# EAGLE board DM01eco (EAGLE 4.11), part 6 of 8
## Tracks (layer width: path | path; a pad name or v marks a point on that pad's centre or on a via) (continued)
DB11-0  (via drill 0.61) (continued)
  Route2 0.152: v163.19,13.97 168.28,13.97 175.26,20.95 181.61,20.95 187.96,27.3 189.87,27.3 192.41,24.77 194.31,26.67 200.03,26.67 200.66,27.3 209.55,27.3 211.46,25.4 255.27,69.22 v255.27,69.85
  Route15 0.152: v67.31,99.06 67.94,99.06 74.3,92.71 74.93,92.71 76.2,91.44 76.2,89.54 89.53,76.2 89.53,75.57 92.08,73.03 93.34,73.03 98.42,67.95 99.69,67.95 v101.6,66.04 | v125.09,42.55 130.18,42.55 147.96,24.77 148.59,24.77 159.38,13.97 v163.19,13.97
  Bottom 0.152: v67.31,99.06 45.72,120.65 48.26,123.19 52.07,123.19 C28.F2 | v101.6,66.04 101.6,65.41 124.46,42.55 v125.09,42.55 | v255.27,69.85 258.44,73.03 269.88,61.59 269.88,59.69 267.97,57.78 269.88,55.88 269.88,55.24 278.13,46.99 v278.13,46.35
DB11-1  (via drill 0.61)
  Top 0.152: v48.26,85.09 58.42,95.25 53.98,99.7 50.8,99.7 46.35,95.25 41.27,100.33 41.27,102.87 52.7,114.3 52.7,116.84 C28.J2 | v165.74,1.91 166.37,1.91 167.64,3.18 169.54,3.18 191.77,25.4 192.41,25.4 203.2,36.2 208.91,36.2 219.07,46.35 219.07,48.89 220.34,50.16 D15.H2
  Route15 0.152: v116.2,24.13 123.19,24.13 130.18,17.14 130.18,15.88 131.44,14.61 133.35,14.61 133.99,13.97 153.67,13.97 v155.57,12.07
  Bottom 0.152: v48.26,85.09 48.26,81.28 59.05,70.48 62.23,73.66 69.85,66.04 69.85,65.41 88.9,46.35 94.61,46.35 116.2,24.77 v116.2,24.13 | v165.74,1.91 v155.57,12.07
DB11-2  (via drill 0.61)
  Top 0.152: v127,34.92 127,35.56 127.64,36.2 132.72,36.2 145.41,48.89 145.41,49.53 146.69,50.8 147.32,50.8 151.13,46.99 153.03,48.89 155.57,48.89 156.84,50.16 D20.H2
  Route15 0.152: v120.02,40.64 124.46,36.2 125.73,36.2 v127,34.92
  Bottom 0.152: v120.02,40.64 117.47,43.18 117.47,48.89 104.78,61.59 98.42,61.59 52.7,107.32 52.7,110.49 C28.L2
DB11-3
  Bottom 0.152: D25.H2 93.34,51.43 93.34,53.98 57.15,90.17 57.15,91.44 56.52,92.08 56.52,93.98 58.42,95.89 53.98,100.33 53.98,102.87 52.7,104.14 C28.N2
DB11-4  (via drill 0.61)
  Top 0.152: v28.57,66.67 28.57,71.75 51.44,94.62 51.44,97.16 52.07,97.79 C28.R2
  Bottom 0.152: v28.57,66.67 28.57,56.52 29.84,55.24 29.84,51.43 D30.H2
DB11-5  (via drill 0.61)
  Top 0.152: v14.61,142.88 14.61,149.22 11.43,152.4 v43.81,184.78 | v53.98,222.25 55.24,222.25 66.67,233.68 66.67,240.03 79.38,252.73 79.38,255.27 80.64,256.54 A26.H2
  Route2 0.152: v53.98,95.89 52.7,94.62 52.7,92.71 C28.T2 | v43.81,184.78 50.8,191.77 50.8,193.04 53.98,196.22 v53.98,222.25
  Bottom 0.152: v53.98,95.89 55.88,97.79 44.45,109.22 38.73,109.22 15.88,132.08 15.88,141.61 v14.61,142.88
DB11-6  (via drill 0.61)
  Top 0.152: v55.24,87 53.34,87 52.7,86.36 C28.V2
  Route2 0.152: v27.3,182.25 27.3,180.97 15.88,169.55 15.88,156.21 v7.62,147.96
  Route15 0.152: v27.3,182.25 28.57,183.52 28.57,204.47 3.17,229.87 3.17,241.94 1.27,243.84 13.97,256.54 17.14,256.54 A31.H2
  Bottom 0.152: v7.62,147.96 7.62,139.7 53.98,93.34 53.98,88.27 v55.24,87
DB_SEL_DEV0  (via drill 0.61)
  Top 0.152: C17.E2 194.94,126.37 193.68,125.09 191.13,125.09 189.23,123.19 186.06,126.37 182.88,126.37 C18.E2 182.25,126.37 179.71,126.37 176.53,123.19 179.71,120.02 v177.8,118.11 | 69.85,126.37 71.75,126.37 74.93,123.19 76.83,125.09 79.38,125.09 80.64,126.37 C26.E2 | 69.85,126.37 68.58,126.37 C27.E2 | C19.E2 169.54,127.64 168.28,128.91 162.56,128.91 161.29,127.64 157.48,127.64 C20.E2 156.84,126.37 153.67,126.37 148.59,121.29 v148.59,120.65 | C25.E2 93.98,127.64 97.79,127.64 99.06,128.91 104.78,128.91 106.05,127.64 C24.E2 106.68,127 109.86,127 111.76,128.91 118.11,128.91 119.38,127.64 C23.E2 | v137.79,122.56 142.88,127.64 144.15,127.64 C21.E2 | 69.85,126.37 v65.41,121.92 | v268.61,275.59 267.33,275.59 262.89,271.14 262.25,271.14 259.71,268.6 257.18,268.6 255.91,267.33 A12.D2
  Route2 0.152: C28.E2 55.24,127.64 51.44,127.64 48.9,130.18 46.99,128.27 43.81,128.27 43.18,127.64 C29.E2 | v296.55,241.94 296.55,241.3 271.14,215.9 271.14,208.91 247.65,185.42 247.65,184.78 244.47,181.61 244.47,177.16 243.84,176.53 238.12,176.53 216.53,154.94 216.53,153.67 208.91,146.05 208.91,144.15 199.39,134.62 198.75,134.62 194.94,130.81 194.94,127.64 C17.E2
  Route15 0.152: v350.52,200.66 353.69,197.49 356.87,197.49 B04.D2
  Bottom 0.152: C30.E2 30.48,126.37 34.29,126.37 35.56,125.09 41.27,125.09 42.55,126.37 C29.E2 | 130.18,125.09 124.46,125.09 123.19,126.37 119.38,126.37 C23.E2 | 130.18,125.09 131.44,126.37 C22.E2 | v137.79,122.56 136.53,122.56 134.62,120.65 130.18,125.09 | v148.59,120.65 147.96,120.65 145.41,123.19 145.41,125.73 144.78,126.37 C21.E2 | C26.E2 81.28,126.37 85.09,126.37 86.36,125.09 92.08,125.09 93.34,126.37 C25.E2 | v177.8,118.11 179.71,120.02 173.99,125.73 170.81,125.73 170.18,126.37 C19.E2 | v65.41,121.92 64.77,122.56 63.5,122.56 59.69,126.37 55.88,126.37 C28.E2 | v350.52,200.66 349.25,200.66 345.44,204.47 340.36,204.47 299.72,245.11 | 299.72,245.11 287.02,257.81 286.38,257.81 v268.61,275.59 | 299.72,245.11 v296.55,241.94
DB_SEL_DEV1  (via drill 0.61)
  Top 0.152: C20.H2 157.48,121.29 161.29,121.29 162.56,122.56 168.28,122.56 169.54,121.29 C19.H2 | C29.H2 43.18,121.29 43.81,121.92 46.99,121.92 48.9,123.83 51.44,121.29 55.24,121.29 C28.H2 55.88,120.02 59.05,120.02 62.23,116.84 64.14,118.75 65.41,118.75 67.94,121.29 C27.H2 | C23.H2 119.38,121.29 123.19,121.29 124.46,122.56 130.18,122.56 131.44,121.29 C22.H2 | 91.44,121.29 89.53,121.29 87,123.83 85.09,121.92 81.92,121.92 81.28,121.29 C26.H2 | 91.44,121.29 93.34,121.29 C25.H2 | 91.44,121.29 97.16,127 102.87,121.29 106.05,121.29 C24.H2 | v148.59,127.64 145.41,124.46 145.41,121.92 144.78,121.29 C21.H2 | v348.62,203.84 348.62,202.56 347.98,201.93 349.88,200.03 347.98,198.12 v347.35,198.12 | v355.6,188.59 356.87,189.87 B04.F2 | v194.94,202.56 194.94,203.84 196.85,205.74 196.85,209.55 v206.38,219.08
  Route2 0.152: C17.H2 194.94,121.29 191.13,121.29 188.59,123.83 184.78,120.02 182.88,120.02 C18.H2 | C21.H2 144.15,120.02 140.34,120.02 139.06,118.75 137.16,118.75 133.35,122.56 132.08,121.29 C22.H2 | 257.18,267.97 257.18,271.14 264.16,278.13 276.86,278.13 v278.13,279.4 | 257.18,267.97 257.18,264.8 255.91,263.52 255.91,260.99 A12.F2 | v165.1,147.32 166.37,148.59 166.37,149.86 171.45,154.94 171.45,158.12 170.18,159.39 175.26,164.47 175.26,166.37 173.35,168.28 175.9,170.81 176.53,170.81 177.8,172.09 177.8,173.99 180.97,177.16 180.97,182.88 193.68,195.58 193.68,201.3 v194.94,202.56 | v206.38,219.08 206.38,221.62 211.46,226.69 212.72,226.69 254,267.97 257.18,267.97
  Bottom 0.152: 173.99,132.08 182.25,123.83 182.25,121.29 C18.H2 | 173.99,132.08 172.09,132.08 166.37,126.37 168.28,124.46 168.28,122.56 169.54,121.29 C19.H2 | C30.H2 30.48,120.02 34.29,120.02 35.56,118.75 41.91,118.75 43.18,120.02 C29.H2 | C27.H2 68.58,120.02 72.39,120.02 73.66,118.75 80.01,118.75 81.28,120.02 C26.H2 | C23.H2 118.75,121.29 114.94,121.29 113.67,122.56 111.12,122.56 107.95,119.38 106.68,120.65 C24.H2 | v148.59,127.64 148.59,126.37 149.86,125.09 150.5,125.09 154.31,121.29 156.84,121.29 C20.H2 | v278.13,279.4 330.2,227.33 330.2,226.06 333.38,222.89 333.38,217.81 346.07,205.11 347.35,205.11 v348.62,203.84 | v347.35,198.12 347.35,196.85 v355.6,188.59 | 173.99,132.08 173.99,134.62 175.9,136.53 v165.1,147.32
DB_SEL_DEV2  (via drill 0.61)
  Top 0.152: C18.K2 182.25,114.94 180.97,116.21 175.26,116.21 173.99,114.94 170.18,114.94 C19.K2 169.54,113.67 167,113.67 v163.83,110.49 | 119.38,117.48 119.38,114.94 C23.K2 | 119.38,117.48 121.28,119.38 123.83,119.38 130.18,113.03 131.44,114.3 C22.K2 | 92.08,116.21 92.71,116.21 93.98,114.94 C25.K2 | 92.08,116.21 86.36,116.21 85.09,114.94 81.28,114.94 C26.K2 80.64,113.67 76.83,113.67 75.56,112.4 73.03,112.4 69.85,115.57 68.58,114.3 C27.K2 67.94,113.67 66.67,112.4 64.14,112.4 62.23,110.49 59.05,113.67 55.88,113.67 C28.K2 | 92.08,116.21 96.52,120.65 102.23,114.94 106.05,114.94 C24.K2 | 119.38,117.48 116.2,120.65 109.22,113.67 v109.22,113.03 | 259.71,261.62 276.86,278.76 276.86,279.4 278.13,280.67 v285.75,280.67 | 259.71,261.62 255.91,257.81 255.91,254.64 A12.J2 | v373.38,196.22 368.94,191.77 367.67,191.77 361.95,186.06 358.77,186.06 357.5,184.78 B04.J2 | v165.1,148.59 165.74,148.59 168.28,151.13 169.54,149.86 169.54,149.22 165.74,145.41 165.74,139.06 144.78,118.11 144.78,114.94 C21.K2 | v219.07,256.54 219.07,258.44 231.14,270.51 v231.78,270.51 | v249.56,255.91 249.56,257.18 251.46,259.08 252.09,259.08 254.63,261.62 259.71,261.62
  Route2 0.152: C17.K2 194.94,114.94 191.13,114.94 188.59,117.48 186.69,115.57 183.51,115.57 182.88,114.94 C18.K2 | C30.K2 30.48,114.94 34.29,114.94 35.56,116.21 41.91,116.21 43.18,114.94 C29.K2 | v165.1,148.59 165.1,154.94 165.74,155.58 165.74,156.21 153.67,168.28 155.57,170.18 155.57,183.52 160.66,188.59 161.29,188.59 193.68,220.98 193.68,227.33 219.07,252.73 v219.07,256.54
  Route15 0.152: C29.K2 43.18,113.67 46.99,113.67 48.26,112.4 54.61,112.4 55.88,113.67 C28.K2
  Bottom 0.152: C22.K2 132.08,114.94 133.99,113.03 137.16,116.21 139.06,116.21 140.34,114.94 144.15,114.94 C21.K2 144.78,114.94 146.69,113.03 149.86,116.21 151.76,116.21 153.03,114.94 156.84,114.94 C20.K2 157.48,113.67 158.12,113.03 161.29,113.03 v163.83,110.49 | v109.22,113.03 107.31,113.03 106.68,113.67 C24.K2 | v285.75,280.67 289.56,280.67 332.74,237.49 332.74,236.86 v373.38,196.22 | v231.78,270.51 232.41,271.14 234.95,271.14 247.01,259.08 247.01,258.44 v249.56,255.91
DB_SEL_DEV3  (via drill 0.61)
  Top 0.152: v46.35,102.87 47.62,102.87 50.8,106.05 53.98,106.05 55.24,107.32 C28.M2 | C26.M2 80.64,108.59 76.83,108.59 74.3,111.12 72.39,109.22 69.22,109.22 68.58,108.59 C27.M2 | 183.51,109.22 180.34,112.4 178.44,112.4 176.53,110.49 175.9,110.49 173.99,108.59 170.18,108.59 C19.M2 169.54,107.32 165.74,107.32 v162.56,104.14 | 183.51,109.22 182.88,108.59 C18.M2 | v189.87,104.78 192.41,107.32 194.94,107.32 C17.M2 | 183.51,109.22 v184.15,109.86 | C24.M2 106.68,107.32 109.86,107.32 113.03,104.14 114.94,106.05 117.47,106.05 118.75,107.32 C23.M2 | v125.73,104.14 128.91,107.32 131.44,107.32 C22.M2 | v138.43,98.43 144.15,104.14 144.15,107.32 C21.M2 144.78,107.32 147.96,107.32 150.5,104.78 151.76,106.05 155.57,106.05 156.84,107.32 C20.M2 157.48,108.59 157.48,111.12 v164.47,118.11 | v109.22,115.57 109.22,114.94 104.14,109.86 99.06,109.86 97.79,108.59 93.98,108.59 C25.M2 | v344.81,162.56 356.87,174.62 356.87,177.16 B04.L2 | v156.84,142.88 156.84,145.41 175.9,164.47 175.9,165.1 v178.44,167.64
  Route2 0.152: C30.M2 30.48,108.59 34.29,108.59 35.56,109.86 41.91,109.86 43.18,108.59 C29.M2 | C28.M2 55.88,107.32 59.05,107.32 62.23,104.14 64.14,106.05 66.67,106.05 67.94,107.32 C27.M2 | v178.44,167.64 198.75,187.96 199.39,187.96 235.59,224.16 v236.85,224.16 | v231.78,231.14 233.68,229.24 246.38,241.94 247.01,241.94 251.46,246.38 254.63,246.38 255.27,247.02 A12.L2
  Route15 0.152: v302.89,209.55 295.27,209.55 292.1,212.72 292.1,214.63 267.97,238.76 267.97,239.4 266.7,240.66 v264.8,240.66
  Bottom 0.152: C26.M2 81.28,108.59 85.09,108.59 87,110.49 87.63,109.86 92.08,109.86 93.34,108.59 C25.M2 | v46.35,102.87 45.09,102.87 43.18,104.78 43.18,107.32 C29.M2 | v189.87,104.78 189.23,104.78 v184.15,109.86 | v125.73,104.14 123.19,106.68 | 123.19,106.68 120.02,106.68 119.38,107.32 C23.M2 | v138.43,98.43 132.72,104.14 132.72,106.68 132.08,107.32 C22.M2 | v162.56,104.14 160.66,102.23 160.02,102.87 159.38,102.87 158.12,104.14 158.12,106.68 157.48,107.32 C20.M2 | v109.22,115.57 109.22,114.94 111.76,112.4 117.47,112.4 123.19,106.68 | v344.81,162.56 344.17,162.56 332.74,173.99 332.74,174.62 328.3,179.07 327.66,179.07 304.8,201.93 304.8,205.11 306.07,206.38 v302.89,209.55 | v264.8,240.66 264.8,241.3 258.44,247.65 255.91,247.65 A12.L2 | v164.47,118.11 167,120.65 155.57,132.08 155.57,135.25 159.38,139.06 158.75,139.7 158.75,140.97 v156.84,142.88 | v236.85,224.16 236.85,225.43 231.78,230.5 v231.78,231.14
DB_SEL_DEV4  (via drill 0.61)
  Top 0.152: C29.P2 43.18,101.6 44.45,102.87 47.62,99.7 50.16,99.7 51.44,100.97 55.24,100.97 C28.P2 55.88,102.23 56.52,102.87 59.69,102.87 62.87,106.05 64.14,106.05 65.41,107.32 67.94,104.78 67.94,102.23 C27.P2 68.58,102.23 72.39,102.23 73.66,103.51 78.74,103.51 v79.38,104.14 | C26.P2 81.28,100.97 84.45,100.97 87.63,97.79 89.53,99.7 92.08,99.7 93.34,100.97 C25.P2 | v100.33,92.08 106.05,97.79 106.05,100.97 C24.P2 | v104.14,89.54 115.57,100.97 118.75,100.97 C23.P2 | v163.83,98.43 164.47,98.43 165.74,99.7 168.28,99.7 169.54,100.97 C19.P2 | v176.53,99.06 178.44,100.97 182.25,100.97 C18.P2 182.88,102.23 183.51,102.87 v185.42,102.87 186.69,102.87 219.07,135.25 219.07,140.34 225.43,146.69 227.97,146.69 244.47,163.19 245.75,163.19 246.38,163.83 v247.01,163.83 | v189.23,98.43 191.77,100.97 194.94,100.97 C17.P2 | v358.77,168.28 358.77,163.19 353.69,158.12 353.06,158.12 351.79,156.84 346.71,156.84 342.9,153.03 342.9,148.59 v337.82,143.51 | v317.5,154.31 317.5,153.67 314.32,150.5 310.51,150.5 v295.27,135.25 | v151.13,92.08 156.84,97.79 156.84,98.43 160.02,101.6 160.02,102.23 157.48,104.78 156.21,103.51 156.21,102.87 156.84,102.23 C20.P2 | v125.09,93.34 124.46,93.34 122.56,95.25 127,99.7 130.18,99.7 131.44,100.97 C22.P2
  Route2 0.152: C22.P2 132.08,102.23 135.89,102.23 137.16,103.51 142.88,103.51 144.15,102.23 C21.P2 | v255.91,233.05 255.91,232.41 v216.53,193.04 | v295.27,135.25 288.29,128.27 283.21,128.27 282.57,127.64 v282.57,127
  Route15 0.152: v176.53,99.06 175.9,99.06 173.99,100.97 170.18,100.97 C19.P2 | v282.57,127 282.57,131.44 273.05,140.97 270.51,140.97 247.65,163.83 v247.01,163.83 | v125.09,93.34 124.46,93.34 118.75,99.06 118.75,100.97 C23.P2
  Bottom 0.152: C30.P2 30.48,102.23 34.29,102.23 39.37,107.32 41.27,105.41 41.27,103.51 42.55,102.23 C29.P2 | C25.P2 93.98,100.97 94.61,100.33 94.61,97.79 v100.33,92.08 102.87,89.54 v104.14,89.54 | v79.38,104.14 79.38,103.51 80.64,102.23 C26.P2 | v163.83,98.43 160.66,101.6 157.48,101.6 C20.P2 | v189.23,98.43 185.42,102.23 v185.42,102.87 | v255.91,233.05 255.27,233.05 253.37,234.95 255.27,236.86 255.27,240.66 A12.N2 | v216.53,193.04 217.81,193.04 v247.01,163.83 | v358.77,168.28 357.5,169.55 357.5,170.81 B04.N2 | v337.82,143.51 334.64,143.51 332.11,146.05 330.2,146.05 328.93,147.32 326.39,147.32 320.04,153.67 318.13,153.67 v317.5,154.31 | v151.13,92.08 145.41,97.79 145.41,99.7 144.78,100.33 144.78,100.97 C21.P2
DB_SEL_DEV5  (via drill 0.61)
  Top 0.152: v353.69,160.02 354.96,160.02 356.87,161.93 356.87,164.47 B04.R2 | v320.04,193.04 318.13,193.04 v307.98,182.88 | v134.62,90.17 136.53,90.17 139.7,93.34 140.97,93.34 | 140.97,93.34 142.88,93.34 144.15,94.62 C21.S2 | v160.02,100.33 159.38,100.33 157.48,98.43 157.48,95.89 C20.S2 | 140.97,93.34 140.97,95.89 142.24,97.16 142.88,97.16 149.86,104.14 151.13,104.14 v151.76,104.78 | v38.1,92.71 38.73,93.34 41.27,93.34 42.55,94.62 C29.S2 | v48.9,90.81 52.7,94.62 55.24,94.62 C28.S2 | v77.47,89.54 79.38,91.44 79.38,93.34 80.64,94.62 C26.S2 81.28,95.89 v85.09,95.89 | v112.39,103.51 111.76,103.51 107.31,99.06 107.31,96.52 106.68,95.89 C24.S2 | v52.07,81.28 52.07,81.92 63.5,93.34 66.67,93.34 67.94,94.62 C27.S2 | v229.87,140.97 v241.3,152.4 | v210.82,125.73 210.19,125.73 193.68,109.22 v193.68,108.59
  Route2 0.152: v168.91,83.82 168.91,84.46 179.07,94.62 182.25,94.62 C18.S2 | C25.S2 93.98,95.89 97.79,95.89 99.06,97.16 104.78,97.16 106.05,95.89 C24.S2 | C22.S2 131.44,94.62 131.44,92.71 129.54,90.81 123.83,90.81 120.65,87.63 117.47,87.63 115.57,89.54 117.47,91.44 117.47,93.34 118.75,94.62 C23.S2 | v283.85,201.93 283.21,202.56 273.05,192.41 273.05,191.14 272.42,190.5 272.42,189.87 271.14,188.59 270.51,188.59 269.88,187.96 269.88,176.53 262.89,169.55 256.54,169.55 249.56,162.56 248.92,162.56 247.65,161.29 247.65,159.39 241.3,153.03 v241.3,152.4 | v229.87,140.97 229.87,139.7 215.26,125.09 212.72,125.09 211.46,126.37 v210.82,125.73 | v193.68,108.59 193.68,106.05 194.94,104.78 193.68,103.51 193.68,99.7 196.22,97.16 194.94,95.89 C17.S2
  Route15 0.152: v307.98,182.88 304.17,182.88 v292.1,194.94 | C18.S2 182.88,94.62 186.06,94.62 190.5,90.17 192.41,90.17 196.22,93.98 195.58,94.62 C17.S2
  Bottom 0.152: v353.69,160.02 353.06,160.02 v320.04,193.04 | v292.1,194.94 292.1,199.39 293.37,200.66 287.65,206.38 | 287.65,206.38 262.25,231.78 260.99,231.78 259.71,233.05 258.44,233.05 255.91,235.59 A12.R2 | v134.62,90.17 133.35,90.17 131.44,92.08 131.44,94.62 C22.S2 | C19.S2 169.54,95.89 168.28,97.16 163.83,97.16 162.56,98.43 162.56,99.06 161.29,100.33 v160.02,100.33 156.21,100.33 v151.76,104.78 | v168.91,83.82 165.74,83.82 158.12,91.44 158.12,93.98 157.48,94.62 C20.S2 | v38.1,92.71 37.47,93.34 35.56,93.34 34.29,94.62 30.48,94.62 C30.S2 | v48.9,90.81 48.26,90.81 46.35,88.9 | 46.35,88.9 43.81,91.44 43.81,93.98 43.18,94.62 C29.S2 | v77.47,89.54 72.39,94.62 68.58,94.62 C27.S2 | v112.39,103.51 113.67,103.51 114.3,102.87 114.3,102.23 118.75,97.79 118.75,95.89 C23.S2 | v85.09,95.89 87,97.79 87.63,97.16 88.27,97.16 92.08,93.34 93.34,94.62 C25.S2 | 46.35,88.9 48.26,87 53.34,87 53.98,86.36 53.98,83.19 v52.07,81.28 | 287.65,206.38 283.85,202.56 v283.85,201.93
DB_SEL_DEV6  (via drill 0.61)
  Top 0.152: v262.25,219.08 268.61,219.08 v274.95,225.43 | v347.98,152.4 353.06,157.48 356.24,157.48 356.87,158.12 B04.T2 | v176.53,85.09 178.44,87 180.97,87 182.25,88.27 C18.U2 182.88,89.54 v184.15,90.81 | v183.51,78.11 190.5,85.09 190.5,86.36 192.41,88.27 194.94,88.27 C17.U2 | v125.73,85.09 127.64,87 130.18,87 131.44,88.27 C22.U2 | v138.43,85.73 140.97,88.27 144.15,88.27 C21.U2 | v166.37,94.62 165.74,94.62 161.29,90.17 158.12,90.17 157.48,89.54 C20.U2 | C30.U2 30.48,89.54 30.48,92.08 38.1,99.7 40.64,99.7 45.72,94.62 43.81,92.71 43.81,90.17 43.18,89.54 C29.U2 | v50.16,85.73 52.7,88.27 55.24,88.27 C28.U2 | 67.94,84.46 66.67,85.73 67.94,87 67.94,88.27 C27.U2 | 67.94,84.46 69.85,86.36 69.85,87 70.48,87.63 72.39,87.63 74.93,85.09 76.83,87 79.38,87 80.64,88.27 C26.U2 | v88.27,85.73 90.81,88.27 93.34,88.27 C25.U2 | v58.42,73.03 60.33,73.03 63.5,76.2 63.5,80.01 67.94,84.46 | v107.31,83.19 111.76,83.19 112.39,83.82 114.3,83.82 114.94,84.46 116.84,84.46 118.75,86.36 118.75,88.27 C23.U2 | v241.3,214.63 241.3,211.46 244.47,208.28 233.04,196.85 232.41,196.85 v229.24,193.68 | v196.85,120.65 196.85,120.02 193.04,116.21 187.96,116.21 186.69,114.94 186.69,113.03 188.59,111.12 180.97,103.51 179.71,103.51 v178.44,102.23
  Route2 0.152: v241.3,214.63 241.3,215.9 245.75,220.34 250.19,220.34 255.27,225.43 255.27,227.97 A12.T2 | v229.24,193.68 229.24,192.41 215.9,179.07 215.9,177.16 220.34,172.72 219.07,171.45 219.07,170.81 215.9,167.64 215.9,162.56 217.17,161.29 212.09,156.21 212.09,154.31 214,152.4 212.09,150.5 210.19,150.5 209.55,149.86 208.28,149.86 197.49,139.06 197.49,138.43 193.68,134.62 193.68,125.09 197.49,121.29 v196.85,120.65
  Bottom 0.152: v262.25,219.08 255.91,225.43 255.91,227.97 A12.T2 | v274.95,225.43 295.91,204.47 295.91,203.2 300.36,198.75 300.99,198.75 306.07,193.68 306.7,193.68 v347.98,152.4 | v183.51,78.11 v176.53,85.09 173.35,88.27 170.18,88.27 C19.U2 169.54,89.54 169.54,91.44 v166.37,94.62 | C21.U2 144.78,88.27 148.59,88.27 149.86,87 155.57,87 156.84,88.27 C20.U2 | v125.73,85.09 122.56,88.27 119.38,88.27 C23.U2 | v138.43,85.73 135.25,82.55 132.72,85.09 132.72,87.63 132.08,88.27 C22.U2 | C29.U2 43.18,88.27 43.81,87.63 46.99,87.63 48.9,85.73 v50.16,85.73 50.16,80.01 57.15,73.03 v58.42,73.03 | v88.27,85.73 87,85.73 85.09,87.63 81.92,87.63 81.28,88.27 C26.U2 | 107.31,85.09 108.58,83.82 109.86,83.82 115.57,78.11 115.57,76.84 109.86,71.12 103.5,77.47 103.5,81.92 97.79,87.63 94.61,87.63 93.98,88.27 C25.U2 | 107.31,85.09 106.68,85.73 106.68,88.27 C24.U2 | v107.31,83.19 107.31,85.09 | v178.44,102.23 178.44,101.6 180.97,99.06 180.97,93.34 183.51,90.81 v184.15,90.81
DF0  (via drill 0.61)
  Top 0.152: v44.45,20.95 46.35,19.05 66.67,39.37 73.03,39.37 76.2,42.55 | 76.2,42.55 79.38,42.55 80.64,43.81 D26.K2 | v118.11,67.95 113.67,67.95 110.49,64.77 104.78,64.77 93.98,53.98 92.71,53.98 91.44,52.7 86.36,52.7 76.2,42.55 | v24.13,267.33 8.26,251.46 5.08,251.46 A32.K2 | v237.49,71.12 211.46,45.09 208.28,45.09 D16.K2 | v277.5,240.66 259.71,222.89 259.71,221.62 247.65,209.55 246.38,209.55 v232.41,195.58 | v239.4,182.88 238.76,182.88 234.31,178.44 234.31,176.53 239.4,171.45 v220.34,152.4 | v219.71,147.96 219.71,141.61 196.22,118.11 196.22,116.21 197.49,114.94 v196.85,114.3 | v168.28,149.22 v161.29,142.24 | v147.32,45.72 146.69,45.09 144.78,45.09 D21.K2
  Route2 0.152: v147.32,45.72 149.22,43.81 149.22,43.18 151.13,41.27 153.03,43.18 158.75,43.18 182.25,66.67 v182.88,66.67
  Bottom 0.152: v44.45,20.95 21.59,43.81 17.78,43.81 D31.K2 | v118.11,67.95 140.97,45.09 144.15,45.09 D21.K2 | v24.13,267.33 39.37,282.57 66.04,255.91 66.04,255.27 66.67,254.64 66.67,252.73 67.94,251.46 A27.K2 68.58,250.19 68.58,247.65 100.97,215.27 100.97,214.63 114.94,200.66 114.94,198.75 109.86,193.68 v161.29,142.24 | 239.4,73.03 v237.49,71.12 | 239.4,73.03 263.52,48.89 264.8,48.89 267.33,46.35 269.88,46.35 271.14,45.09 D11.K2 | v277.5,240.66 277.5,241.3 271.78,247.02 271.78,250.19 A11.K2 | v232.41,195.58 230.5,193.68 235.59,188.59 236.22,188.59 237.49,187.33 237.49,186.06 238.76,184.78 238.76,183.52 v239.4,182.88 | v220.34,152.4 217.81,149.86 v219.71,147.96 | v196.85,114.3 198.12,114.3 | 198.12,114.3 213.36,99.06 213.36,98.43 214.63,97.16 215.26,97.16 239.4,73.03 | v168.28,149.22 169.54,149.22 180.97,137.8 180.97,135.25 179.71,133.98 179.71,132.72 198.12,114.3 | v182.88,66.67 203.2,46.35 204.47,46.35 205.1,45.72 207.01,45.72 207.65,45.09 D16.K2
DF1  (via drill 0.61)
  Top 0.152: v242.57,10.16 246.38,10.16 269.88,33.66 269.88,36.2 271.14,37.47 D11.M2 | v41.27,17.78 52.7,6.35 78.11,31.75 78.74,31.75 80.01,33.02 80.01,36.83 80.64,37.47 D26.M2 | v210.82,33.02 207.01,33.02 203.84,29.84 203.2,29.84 186.69,13.34 184.78,13.34 v178.44,6.99 | v34.92,271.78 34.29,271.14 29.21,271.14 24.13,266.06 23.5,266.06 5.08,247.65 5.08,245.11 A32.M2 | v271.14,240.03 271.14,243.84 A11.M2 | v190.5,290.19 154.94,290.19 v89.53,224.79 | v8.26,106.68 8.26,107.95 28.57,128.27 30.48,128.27 31.75,129.54 31.11,130.18 31.75,130.81 31.75,131.44 41.27,140.97 44.45,140.97 75.56,172.09 v76.2,172.09
  Route2 0.152: D21.M2 144.15,38.73 140.34,38.73 137.79,41.27 135.89,39.37 129.54,39.37 123.19,33.02 116.84,33.02 110.49,26.67 101.6,26.67 93.34,34.92 92.08,33.66 88.27,33.66 82.55,39.37 81.28,38.1 D26.M2 | v61.59,191.77 62.87,191.77 76.83,205.74 76.83,210.19 77.47,210.82 77.47,212.72 v89.53,224.79
  Route15 0.152: v229.24,282.57 225.43,278.76 220.98,278.76 219.71,280.03 201.93,280.03 200.66,281.3 199.39,281.3 v190.5,290.19
  Bottom 0.152: 214.63,34.92 215.26,34.29 215.9,34.29 222.25,27.94 222.25,27.3 236.85,12.7 240.03,12.7 v242.57,10.16 | 214.63,34.92 212.09,37.47 208.28,37.47 D16.M2 | v41.27,17.78 21.59,37.47 17.78,37.47 D31.M2 17.14,38.73 17.14,41.91 3.17,55.88 3.17,109.22 4.45,110.49 v8.26,106.68 | 214.63,34.92 212.09,32.38 211.46,33.02 v210.82,33.02 | v178.44,6.99 156.84,28.58 156.84,29.84 153.03,33.66 151.76,33.66 148.59,36.83 145.41,36.83 144.78,37.47 D21.M2 | v34.92,271.78 43.81,271.78 66.67,248.92 | 66.67,248.92 66.67,246.38 67.94,245.11 A27.M2 | v271.14,240.03 271.14,241.3 229.87,282.57 v229.24,282.57 | v89.53,224.79 89.53,226.06 66.67,248.92 | v76.2,172.09 81.28,177.16 69.85,188.59 64.77,188.59 v61.59,191.77
DF2  (via drill 0.61)
  Top 0.152: v238.12,5.08 241.94,5.08 266.7,29.84 269.88,29.84 271.14,31.12 D11.P2 | v46.35,13.97 59.69,13.97 v78.74,33.02 | v113.67,3.18 130.81,20.32 135.89,20.32 140.97,25.4 139.7,26.67 139.7,29.21 141.6,31.12 144.15,31.12 D21.P2 | v198.75,33.02 194.31,33.02 188.59,27.3 187.96,27.3 177.8,17.14 177.8,12.7 v172.09,6.99 | v34.29,264.16 8.89,238.76 5.08,238.76 A32.P2 | v233.04,208.28 233.04,208.91 254.63,230.5 260.35,230.5 267.33,237.49 271.14,237.49 A11.P2 | v134.62,283.21 128.27,283.21 120.02,274.95 114.3,274.95 110.49,271.14 104.14,271.14 72.39,239.4 69.22,239.4 68.58,238.76 A27.P2 | v3.17,53.98 3.17,83.82 12.7,93.34 12.7,94.62 15.88,97.79 15.88,102.87 25.4,112.4 25.4,113.67 28.57,116.84 28.57,121.92 41.91,135.25 v42.55,135.25 | v11.43,172.72 12.06,172.72 31.75,192.41 31.75,193.68 v33.02,194.94
  Route15 0.152: v233.04,208.28 226.06,208.28 225.43,208.91 222.88,208.91 212.72,219.08 211.46,219.08 210.19,220.34 203.2,220.34 196.85,226.69 191.13,226.69 168.28,249.56 v168.28,250.19
  Bottom 0.152: 214,28.58 237.49,5.08 v238.12,5.08 | 214,28.58 212.09,30.48 211.46,30.48 210.82,31.12 208.28,31.12 D16.P2 | v46.35,13.97 45.09,13.97 42.55,16.51 41.27,16.51 40.64,17.14 35.56,17.14 21.59,31.12 17.78,31.12 D31.P2 17.14,32.38 17.14,35.56 3.17,49.53 v3.17,53.98 | v78.74,33.02 80.01,33.02 80.64,32.38 D26.P2 81.28,31.12 81.92,30.48 85.09,30.48 112.39,3.18 v113.67,3.18 | 214,28.58 210.82,25.4 202.56,33.66 200.66,33.66 199.39,32.38 v198.75,33.02 | v172.09,6.99 157.48,21.59 156.84,21.59 152.4,26.04 152.4,26.67 148.59,30.48 145.41,30.48 144.78,31.12 D21.P2 | v34.29,264.16 36.83,266.7 63.5,240.03 66.67,240.03 67.94,238.76 A27.P2 | v168.28,250.19 167.64,250.19 v134.62,283.21 | v42.55,135.25 42.55,136.53 37.47,141.61 34.29,141.61 7.62,168.28 11.43,172.09 v11.43,172.72 | v33.02,194.94 32.38,194.94 28.57,198.75 28.57,206.38 22.86,212.09 22.86,217.17 5.71,234.31 5.71,236.86 5.08,237.49 A32.P2
GND  (via drill 0.61)
  Top 0.508: D30.L2 26.67,40.64 26.67,35.56 D30.N2 26.67,34.29 26.67,29.21 D30.R2 26.67,27.94 23.5,27.94 18.41,22.86 18.41,20.32 17.78,19.69 D31.U2 | D31.R2 13.97,29.21 13.97,34.29 D31.N2 13.97,35.56 13.97,40.64 D31.L2 13.97,41.91 13.97,46.99 D31.J2 13.97,48.26 13.97,53.34 D31.F2 | D30.C2 29.84,62.87 29.84,59.05 28.57,57.78 28.57,55.88 27.3,54.61 D30.F2 | 36.83,22.86 38.73,24.77 38.73,27.3 39.37,27.94 D29.R2 39.37,29.21 39.37,34.29 D29.N2 | 36.83,22.86 33.66,19.69 30.48,19.69 D30.U2 | D29.L2 39.37,41.91 39.37,46.99 D29.J2 39.37,48.26 39.37,53.34 D29.F2 40.01,54.61 41.27,55.88 41.27,57.78 42.55,59.05 42.55,59.69 | 36.83,22.86 40.01,19.69 42.55,19.69 D29.U2 43.18,18.41 46.35,18.41 47.62,17.14 50.16,17.14 51.44,18.41 55.24,18.41 D28.U2 | 42.55,59.69 42.55,62.87 D29.C2 | 42.55,59.69 31.11,48.26 27.3,48.26 D30.J2 | D20.N2 153.67,34.29 149.86,34.29 146.05,30.48 142.88,30.48 141.6,29.21 D21.R2 | D20.C2 156.84,62.87 156.84,59.05 155.57,57.78 155.57,55.88 154.31,54.61 D20.F2 | D21.F2 141.6,54.61 141.6,58.42 142.88,59.69 142.88,61.59 144.15,62.87 D21.C2 | D22.F2 128.91,54.61 128.91,58.42 130.18,59.69 130.18,61.59 131.44,62.87 D22.C2 | D22.J2 128.27,46.99 128.27,41.91 D22.L2 128.27,40.64 127.64,40.01 124.46,40.01 120.02,35.56 116.2,35.56 D23.N2 115.57,34.29 115.57,29.21 D23.R2 115.57,27.94 112.39,27.94 109.86,25.4 109.86,24.77 109.22,24.13 108.58,24.13 107.31,22.86 107.31,20.32 106.68,19.69 D24.U2 | D28.J2 52.07,46.99 52.07,41.91 D28.L2 | D28.C2 55.24,62.87 55.24,60.32 53.34,58.42 53.34,55.24 52.7,54.61 D28.F2 | D25.N2 90.17,34.29 90.17,29.21 D25.R2 90.17,27.94 88.9,26.67 90.17,25.4
  Top 0.508: 93.34,22.23 93.34,19.69 D25.U2 | 93.34,22.23 90.17,25.4 | 93.34,22.23 99.06,27.94 102.87,27.94 D24.R2 | 90.17,25.4 84.45,19.69 81.28,19.69 D26.U2 | 64.77,44.45 64.77,41.91 D27.L2 | 64.77,44.45 64.77,46.99 D27.J2 | D27.C2 67.94,62.87 67.94,59.05 66.67,57.78 66.67,55.88 65.41,54.61 D27.F2 | 64.77,44.45 73.66,53.34 77.47,53.34 D26.F2 78.11,54.61 79.38,55.88 79.38,59.69 80.64,60.96 80.64,62.87 D26.C2 | D24.N2 103.5,35.56 107.31,35.56 111.76,40.01 114.94,40.01 115.57,40.64 D23.L2 116.2,41.91 116.2,46.99 D23.J2 115.57,46.99 111.76,46.99 110.49,45.72 105.41,45.72 104.78,45.09 104.78,43.18 103.5,41.91 D24.L2 | D24.C2 106.05,62.87 106.05,59.05 104.78,57.78 104.78,55.88 103.5,54.61 D24.F2 102.87,53.34 99.06,53.34 90.17,44.45 | D26.N2 78.11,35.56 78.11,37.47 80.01,39.37 85.72,39.37 86.36,40.01 89.53,40.01 90.17,40.64 D25.L2 90.17,41.91 90.17,44.45 | 90.17,44.45 90.17,46.99 D25.J2 | D25.C2 93.34,62.87 93.34,59.05 92.08,57.78 92.08,55.88 90.81,54.61 D25.F2 | D03.C2 372.75,62.87 372.75,59.05 371.48,57.78 371.48,55.88 370.2,54.61 D03.F2 | v394.33,56.52 398.14,60.32 398.14,62.87 D01.C2 | D02.J2 382.27,48.26 382.27,53.34 D02.F2 | 394.97,31.12 394.97,34.29 D01.N2 | 394.97,31.12 394.97,29.21 D01.R2 | D01.J2 394.97,46.99 394.97,41.91 D01.L2 | 394.97,31.12 386.08,22.23 386.08,19.69 D02.U2 385.44,19.69 381.63,19.69 379.1,22.23 377.19,20.32 374.01,20.32 373.38,19.69 D03.U2 | D04.U2 360.68,19.69 360.68,22.23 365.76,27.3 368.94,27.3 369.57,27.94 D03.R2 369.57,29.21 369.57,34.29 D03.N2 | D07.J2 318.77,48.26 318.77,53.34 D07.F2 319.4,54.61 320.68,55.88 320.68,57.78 321.94,59.05 321.94,62.87 D07.C2
  Top 0.508: D06.C2 334.64,62.87 334.64,59.05 333.38,57.78 333.38,55.88 332.11,54.61 D06.F2 | D05.F2 344.81,54.61 344.81,58.42 346.07,59.69 346.07,61.59 347.35,62.87 D05.C2 | D18.F2 179.71,54.61 179.71,58.42 180.97,59.69 180.97,61.59 182.25,62.87 D18.C2 | D19.F2 167,54.61 167,56.52 168.91,58.42 168.91,62.23 169.54,62.87 D19.C2 | 179.07,44.45 179.07,41.91 D18.L2 | 179.07,44.45 179.07,46.99 D18.J2 | 179.07,44.45 187.96,53.34 191.77,53.34 D17.F2 192.41,53.98 193.68,55.24 193.68,59.69 194.94,60.96 194.94,62.87 D17.C2 | v215.9,33.02 217.17,34.29 D15.N2 | D16.C2 207.65,62.87 207.65,59.05 206.38,57.78 206.38,55.88 205.1,54.61 D16.F2 204.47,53.34 200.66,53.34 191.77,44.45 | v204.47,37.47 204.47,40.64 D16.L2 | v156.84,22.86 156.84,19.69 D20.U2 157.48,19.69 160.66,19.69 165.74,24.77 165.74,27.3 166.37,27.94 D19.R2 167,29.21 167,29.84 167.64,30.48 172.09,30.48 175.26,33.66 178.44,33.66 179.07,34.29 D18.N2 179.71,35.56 180.97,36.83 184.15,36.83 187.96,40.64 191.77,40.64 D17.L2 191.77,41.91 191.77,44.45 | 191.77,44.45 191.77,46.99 D17.J2 | D14.F2 230.5,54.61 230.5,58.42 231.78,59.69 231.78,60.96 233.68,62.87 D14.C2 | D15.C2 220.34,62.87 220.34,59.05 217.81,56.52 217.81,54.61 D15.F2 217.17,53.34 v215.9,52.07 | D11.U2 271.14,18.41 267.33,18.41 262.89,13.97 260.99,13.97 257.81,17.14 259.08,18.41 D12.U2 | D05.N2 344.17,34.29 344.17,29.21 D05.R2 344.17,27.94 341,27.94 332.74,19.69 | 307.98,26.67 307.98,20.95 309.25,19.69 D08.U2 | 307.98,26.67 306.7,27.94 D08.R2 | 318.77,31.12 318.77,34.29 D07.N2 318.77,35.56 318.77,40.64 D07.L2 | 318.77,31.12 318.77,29.21 D07.R2 | 328.93,22.86 326.39,20.32 323.21,20.32 322.58,19.69 D07.U2
  Top 0.508: 328.93,22.86 331.47,25.4 331.47,27.94 D06.R2 | 332.74,19.69 332.11,19.69 328.93,22.86 | 332.74,19.69 334.64,19.69 D06.U2 | 307.98,26.67 314.32,26.67 318.77,31.12 | D12.J2 255.27,46.99 255.27,41.91 D12.L2 | D12.C2 258.44,62.87 258.44,59.05 257.18,57.78 257.18,55.88 255.91,54.61 D12.F2 | D08.C2 309.25,62.87 309.25,59.05 307.98,57.78 307.98,55.88 306.7,54.61 D08.F2 | 293.37,38.1 293.37,35.56 D09.N2 | 293.37,38.1 293.37,40.64 D09.L2 | 293.37,38.1 302.26,46.99 306.07,46.99 D08.J2 | D12.R2 255.91,29.21 255.91,31.12 258.44,33.66 259.08,33.66 259.71,34.29 259.71,35.56 258.44,36.83 255.91,34.29 D12.N2 | 394.97,252.73 394.97,248.28 A01.L2 | 394.97,252.73 394.97,253.37 A01.J2 | A05.U2 347.98,224.79 347.98,221.62 351.79,217.81 353.06,217.81 353.69,218.44 355.6,218.44 358.77,221.62 358.77,223.52 360.05,224.79 A04.U2 | A04.R2 356.87,235.59 356.87,240.66 A04.N2 357.5,241.94 361.31,241.94 369.57,250.19 | v393.06,201.93 390.52,201.93 389.89,201.3 386.71,201.3 386.08,200.66 B02.C2 | 382.27,240.03 382.27,240.66 A02.N2 382.27,241.94 382.27,244.47 | 382.27,240.03 382.27,235.59 A02.R2 | 382.27,244.47 382.27,247.02 A02.L2 | 369.57,244.47 369.57,241.94 A03.N2 | 369.57,244.47 369.57,247.02 A03.L2 369.57,248.28 369.57,250.19 | 369.57,250.19 369.57,253.37 A03.J2 369.57,254.64 369.57,259.71 A03.F2 370.2,260.99 371.48,262.25 371.48,264.16 372.75,265.43 372.75,267.97 | 372.75,267.97 372.75,269.24 A03.C2 | 369.57,244.47 378.46,253.37 382.27,253.37 A02.J2 | 382.27,240.03 377.82,240.03 374.65,236.86 371.48,236.86 370.2,235.59 A03.R2 | 394.97,252.73 390.52,252.73 382.27,244.47 | A09.R2 293.37,235.59 293.37,240.66 A09.N2
  Top 0.508: v280.04,238.76 280.04,240.03 280.67,240.66 A10.N2 | A11.L2 267.97,248.28 267.97,253.37 A11.J2 268.61,254.64 272.42,254.64 283.85,266.06 | v266.7,239.4 267.97,240.66 A11.N2 | A10.L2 280.67,248.28 280.67,253.37 A10.J2 | 283.85,266.06 283.85,265.43 282.57,264.16 282.57,262.25 281.31,260.99 A10.F2 | 283.85,266.06 283.85,269.24 A10.C2 | A08.C2 309.25,269.24 309.25,265.43 307.98,264.16 307.98,262.89 306.07,260.99 A08.F2 | A08.U2 309.25,226.06 309.25,229.87 305.44,233.68 306.07,234.31 A08.R2 306.07,235.59 306.07,240.66 A08.N2 306.07,241.94 306.07,247.02 A08.L2 306.7,248.28 310.51,248.28 318.77,256.54 | A07.L2 318.77,248.28 318.77,253.37 A07.J2 318.77,254.64 318.77,256.54 | 318.77,256.54 318.77,259.71 A07.F2 319.4,260.99 320.68,262.25 | 320.68,262.25 320.68,264.16 321.94,265.43 321.94,269.24 A07.C2 | A07.U2 322.58,226.06 323.21,226.69 319.4,230.5 319.4,234.31 A07.R2 319.4,235.59 323.21,235.59 331.47,243.84 | 331.47,243.84 331.47,241.94 A06.N2 332.11,241.94 335.92,241.94 344.17,250.19 | 331.47,243.84 331.47,247.02 A06.L2 | 331.47,257.18 331.47,259.71 A06.F2 | 331.47,255.27 331.47,257.18 | 331.47,255.27 331.47,254.64 A06.J2 | 331.47,257.18 337.82,263.52 | 337.82,263.52 343.54,269.24 347.35,269.24 A05.C2 | A04.L2 356.87,248.28 356.87,253.37 A04.J2 356.87,254.64 356.87,259.08 | 356.87,259.08 356.87,259.71 A04.F2 357.5,260.99 358.77,262.25 358.77,264.16 359.41,264.8 | 359.41,264.8 360.05,265.43 360.05,269.24 A04.C2 | A05.R2 344.17,235.59 344.17,240.66 A05.N2 344.17,241.94 344.17,247.02 A05.L2 344.17,248.28 344.17,250.19 | 344.17,250.83 344.17,250.19 | 344.17,250.83 344.17,253.37 A05.J2
  Top 0.508: 356.87,259.08 352.43,259.08 344.17,250.83 | 337.82,263.52 333.38,267.97 334.64,269.24 A06.C2 | 320.68,262.25 329.56,253.37 331.47,255.27 | A09.F2 294,260.99 294,264.8 295.27,266.06 295.27,267.97 296.55,269.24 A09.C2 | 372.75,267.97 367.67,267.97 364.49,264.8 359.41,264.8 | v243.21,198.75 244.47,198.75 245.75,200.03 B13.C2 | v227.33,198.12 231.78,198.12 233.04,199.39 B14.C2 | B08.C2 309.25,199.39 307.98,198.12 303.53,198.12 302.89,197.49 300.36,200.03 297.18,200.03 B09.C2 296.55,199.39 294,199.39 v290.19,195.58 | B10.C2 283.85,199.39 280.04,199.39 273.05,192.41 269.88,192.41 267.97,194.31 269.88,196.22 269.88,198.12 271.14,199.39 B11.C2 | A21.N2 141.6,241.94 141.6,243.84 143.51,245.75 149.22,245.75 149.86,246.38 153.03,246.38 153.67,247.02 A20.L2 | A21.C2 144.15,269.24 144.15,265.43 142.88,264.16 142.88,262.25 141.6,260.99 A21.F2 | 156.84,266.7 156.84,265.43 155.57,264.16 155.57,262.25 154.31,260.99 A20.F2 153.67,259.71 153.67,254.64 A20.J2 154.31,254.64 158.12,254.64 165.1,261.62 168.28,261.62 169.54,262.89 A19.E2 170.18,264.16 173.99,264.16 177.8,267.97 180.97,267.97 182.25,269.24 A18.C2 | 156.84,266.7 156.84,269.24 A20.C2 | 156.84,266.7 163.19,273.05 165.74,270.51 169.54,270.51 A19.C2 | A15.J2 217.81,254.64 220.98,254.64 v223.52,257.18 231.78,265.43 231.78,267.97 233.04,269.24 A14.C2 | v226.06,234.31 229.24,237.49 233.04,237.49 A14.P2 233.68,238.76 233.68,241.3 v236.85,244.47 | v254,272.41 251.46,272.41 250.19,271.14 247.01,271.14 246.38,270.51 A13.C2 | A23.C2 118.75,269.24 118.75,265.43 117.47,264.16 117.47,262.25 116.2,260.99 A23.F2 115.57,259.71 111.76,259.71 102.87,250.83
  Top 0.508: 102.87,250.83 102.87,248.28 A24.L2 | 102.87,250.83 102.87,253.37 A24.J2 | A26.N2 78.11,241.94 78.11,243.84 80.01,245.75 85.72,245.75 86.36,246.38 89.53,246.38 90.17,247.02 A25.L2 90.17,248.28 90.17,250.83 | 90.17,250.83 90.17,253.37 A25.J2 | 90.17,250.83 106.05,266.7 106.05,269.24 A24.C2 | v100.33,196.22 102.23,198.12 104.78,198.12 106.05,199.39 B24.C2 106.68,200.66 107.31,201.3 110.49,201.3 111.76,202.56 113.03,202.56 114.94,200.66 118.75,200.66 B23.C2 | B19.C2 170.18,200.66 173.99,200.66 175.26,201.93 181.61,201.93 182.88,200.66 B18.C2 | v191.77,198.75 192.41,199.39 194.94,199.39 B17.C2 | v142.88,198.12 144.15,199.39 B21.C2 | A32.R2 1.27,235.59 1.27,240.66 A32.N2 1.27,241.94 1.27,247.02 A32.L2 1.27,248.28 1.27,253.37 A32.J2 1.27,254.64 1.27,259.71 A32.F2 | 13.97,237.49 13.97,240.66 A31.N2 | 13.97,237.49 13.97,235.59 A31.R2 | A31.J2 13.97,253.37 13.97,248.28 A31.L2 | 13.97,237.49 5.08,228.6 5.08,226.06 A32.U2 | A28.L2 52.07,248.28 52.07,253.37 A28.J2 | 39.37,259.08 39.37,259.71 A29.F2 | 39.37,259.08 39.37,254.64 A29.J2 | 26.67,250.83 26.67,248.28 A30.L2 | 26.67,250.83 26.67,253.37 A30.J2 | A30.C2 29.84,269.24 29.84,265.43 28.57,264.16 28.57,262.25 27.3,260.99 A30.F2 | 36.2,259.08 34.92,259.08 26.67,250.83 | 36.2,259.08 39.37,259.08 | 36.2,259.08 42.55,265.43 42.55,269.24 A29.C2 | v9.53,198.12 11.43,196.22 13.34,198.12 15.88,198.12 17.14,199.39 B31.C2 | 46.35,187.96 44.45,186.06 41.27,186.06 40.01,184.78 B29.J2 | 46.35,187.96 55.24,196.85 55.24,199.39 B28.C2 55.88,200.66 59.69,200.66 77.47,218.44 | A30.U2 30.48,226.06 30.48,228.6 35.56,233.68 38.73,233.68 39.37,234.31 A29.R2 39.37,235.59 39.37,240.66 A29.N2
  Top 0.508: 77.47,218.44 76.83,219.08 79.38,221.62 79.38,223.52 80.64,224.79 A26.U2 | 77.47,218.44 79.38,216.53 81.28,216.53 88.27,223.52 90.17,223.52 91.44,224.79 93.34,224.79 A25.U2 | A27.N2 64.77,240.66 64.77,235.59 A27.R2 64.77,234.31 60.96,234.31 55.24,228.6 | 55.24,228.6 55.24,229.87 52.7,232.41 | 55.24,228.6 55.24,226.06 A28.U2 | 52.7,232.41 51.44,233.68 52.07,234.31 A28.R2 | v76.2,197.49 78.11,199.39 80.64,199.39 B26.C2 | 52.7,232.41 46.35,226.06 43.18,226.06 A29.U2 | 46.35,187.96 v45.72,187.96 | v87.63,196.22 90.81,199.39 93.34,199.39 B25.C2 | A28.C2 55.24,269.24 55.24,265.43 53.98,264.16 53.98,262.25 52.7,260.99 A28.F2 | B07.C2 322.58,200.66 326.39,200.66 327.66,201.93 329.56,201.93 332.74,198.75 334.64,200.66 B06.C2 | v374.65,179.07 370.2,174.62 370.2,172.09 B03.N2 | v376.56,161.93 373.38,158.75 373.38,156.21 B03.U2 | v368.94,193.04 368.94,193.68 372.75,197.49 372.75,199.39 B03.C2 | 241.3,130.81 241.94,131.44 243.84,131.44 245.11,132.72 245.75,132.72 C13.C2 | 241.3,130.81 241.3,129.54 243.84,127 245.11,128.27 250.82,128.27 254,131.44 257.18,131.44 258.44,132.72 C12.C2 | v379.73,129.54 381.63,131.44 384.18,131.44 385.44,132.72 C02.C2 | v391.8,128.91 395.61,132.72 398.14,132.72 C01.C2 | C07.C2 322.58,133.98 321.31,135.25 314.96,135.25 313.69,133.98 309.88,133.98 C08.C2 309.25,133.35 306.7,133.35 303.53,130.18 300.99,132.72 297.18,132.72 C09.C2 | v278.13,131.44 282.57,131.44 283.85,132.72 C10.C2 | v377.19,140.34 374.01,137.16 374.01,134.62 373.38,133.98 C03.C2 | v227.33,129.54 229.24,131.44 231.78,131.44 233.04,132.72 C14.C2 | v214.63,129.54 216.53,131.44 219.07,131.44 220.34,132.72 C15.C2
  Top 0.508: C21.C2 144.15,132.72 142.88,131.44 140.34,131.44 138.43,129.54 135.25,132.72 132.08,132.72 C22.C2 131.44,132.72 131.44,128.91 130.18,127.64 v130.18,127 | C18.C2 182.25,132.72 178.44,132.72 173.99,128.27 172.09,128.27 168.91,131.44 170.18,132.72 C19.C2 | v189.23,129.54 192.41,132.72 194.94,132.72 C17.C2 | v99.69,131.44 104.78,131.44 106.05,132.72 C24.C2 | v11.43,129.54 13.34,131.44 15.88,131.44 17.14,132.72 C31.C2 | 50.8,166.37 40.01,155.58 40.01,153.03 B29.V2 | 50.8,166.37 53.98,166.37 55.24,167.64 B28.P2 | 50.8,166.37 64.77,180.34 64.77,183.52 B27.J2 | C27.C2 67.94,132.72 64.14,132.72 59.69,128.27 52.07,128.27 50.16,130.18 51.44,131.44 53.98,131.44 55.24,132.72 C28.C2 | v68.58,163.83 70.48,161.93 v65.41,156.84 | v74.93,131.44 75.56,131.44 76.83,132.72 80.64,132.72 C26.C2 | 241.3,130.81 240.03,130.81 v239.4,131.44 | C32.F2 1.91,124.46 1.91,128.27 3.17,129.54 3.17,131.44 4.45,132.72 C32.C2
  Route2 0.508: D21.L2 140.97,41.91 140.97,46.99 D21.J2 | D23.F2 115.57,53.34 115.57,48.26 D23.J2 | D19.J2 166.37,46.99 166.37,41.91 D19.L2 | D18.F2 179.71,53.34 179.71,48.26 D18.J2 | v209.55,20.95 208.28,19.69 D16.U2 | D16.N2 204.47,34.29 204.47,29.21 D16.R2 | D21.U2 144.78,19.69 144.78,22.23 149.86,27.3 153.03,27.3 153.67,27.94 D20.R2 154.31,28.58 156.21,30.48 154.31,32.38 154.31,34.29 D20.N2 | D17.U2 194.94,19.69 191.13,19.69 188.59,22.23 186.69,20.32 183.51,20.32 182.88,19.69 D18.U2 | v227.33,52.7 227.97,53.34 229.87,53.34 D14.F2 | D13.J2 242.57,46.99 242.57,41.91 D13.L2 | D13.R2 242.57,29.21 242.57,34.29 D13.N2 | B02.C2 385.44,200.66 385.44,204.47 386.08,205.11 386.71,205.11 387.35,205.74 387.35,220.98 384.81,223.52 386.08,224.79 A02.U2 | A11.U2 271.78,226.06 273.69,226.06 274.32,226.69 275.59,226.69 280.04,231.14 280.04,233.68 280.67,234.31 A10.R2 | 280.67,247.02 280.04,246.38 276.86,246.38 273.69,243.21 271.78,243.21 270.51,241.94 268.61,241.94 A11.N2 | 280.67,247.02 A10.L2 280.67,247.02 | 280.67,247.02 280.67,241.94 A10.N2 | 160.02,133.98 161.29,133.98 162.56,135.25 168.28,135.25 169.54,133.98 C19.C2 | 160.02,133.98 157.48,133.98 C20.C2 | 160.02,133.98 153.67,127.64 148.59,132.72 144.78,132.72 C21.C2 | C26.C2 81.28,133.98 85.09,133.98 86.36,135.25 92.71,135.25 93.98,133.98 C25.C2
  Route15 0.508: D22.U2 131.44,19.69 131.44,23.5 130.18,24.77 130.18,26.67 128.91,27.94 D22.R2 | D21.J2 140.97,48.26 140.97,53.34 D21.F2 140.97,54.61 137.79,54.61 132.72,59.69 132.72,62.23 132.08,62.87 D22.C2 | D13.F2 242.57,54.61 242.57,57.15 237.49,62.23 234.31,62.23 233.68,62.87 D14.C2 | D14.L2 230.5,40.64 233.68,40.64 239.4,34.92 242.57,34.92 D13.N2 | A02.U2 385.44,226.06 385.44,229.87 384.18,231.14 384.18,233.05 382.9,234.31 A02.R2 | A10.U2 283.85,226.06 283.85,229.87 282.57,231.14 282.57,233.05 281.31,234.31 A10.R2 | v295.27,231.78 295.27,233.05 294,234.31 A09.R2 | A06.N2 331.47,240.66 331.47,235.59 A06.R2 332.11,234.31 333.38,233.05 333.38,231.14 334.64,229.87 334.64,226.06 A06.U2 | A13.C2 245.75,270.51 241.94,270.51 240.66,271.78 238.12,271.78 235.59,269.24 233.68,269.24 A14.C2 | v254,272.41 255.91,270.51 258.44,270.51 A12.C2 | A24.R2 102.87,235.59 102.87,240.66 A24.N2 | A30.R2 26.67,235.59 26.67,240.66 A30.N2 | A27.U2 67.94,226.06 67.94,229.87 66.67,231.14 66.67,233.05 65.41,234.31 A27.R2 | A27.J2 64.77,253.37 64.77,248.28 A27.L2 | B27.C2 67.94,200.66 67.94,204.47 66.67,205.74 66.67,217.17 59.69,224.16 56.52,224.16 55.88,224.79 A28.U2 | C03.C2 372.75,132.72 372.75,130.18 370.2,127.64 369.57,128.27 368.3,128.27 364.49,132.08 361.31,132.08 360.68,132.72 C04.C2 | B28.V2 52.07,151.77 48.9,151.77 45.09,147.96 40.01,153.03 B29.V2
  Bottom 0.508: D31.U2 17.14,19.69 17.14,23.5 15.88,24.77 15.88,26.67 14.61,27.94 D31.R2 | D30.J2 26.67,48.26 26.67,53.34 D30.F2 26.67,54.61 23.5,54.61 15.24,62.87 | 11.43,59.69 13.34,57.78 13.34,55.24 13.97,54.61 D31.F2 | 11.43,59.69 8.26,62.87 5.08,62.87 D32.C2 | 15.24,62.87 14.61,62.87 11.43,59.69 | 15.24,62.87 17.14,62.87 D31.C2 | D29.L2 39.37,40.64 39.37,35.56 D29.N2 | D23.U2 118.75,19.69 118.75,23.5 117.47,24.77 117.47,26.04 115.57,27.94 D23.R2 | D22.R2 128.27,29.21 124.46,29.21 120.65,33.02 117.47,33.02 116.2,34.29 D23.N2 | D20.N2 153.67,35.56 153.67,40.64 D20.L2 | D21.R2 140.97,29.21 140.97,34.29 D21.N2 140.97,35.56 137.16,35.56 133.35,39.37 130.18,39.37 128.91,40.64 D22.L2 128.27,40.64 128.27,35.56 D22.N2 | D20.J2 153.67,48.26 153.67,53.34 D20.F2 153.67,54.61 150.5,54.61 145.41,59.69 145.41,62.23 144.78,62.87 D21.C2 | 119.38,59.69 119.38,62.87 D23.C2 | 119.38,59.69 127.64,51.43 127.64,48.89 128.27,48.26 D22.J2 | 112.39,66.67 116.84,71.12 120.65,71.12 123.83,67.95 129.54,67.95 131.44,66.04 131.44,64.14 D22.C2 | 119.38,59.69 112.39,66.67 | 52.07,31.75 52.07,34.29 D28.N2 52.07,35.56 52.07,38.1 | 52.07,31.75 52.07,29.21 D28.R2 | 52.07,38.1 52.07,40.64 D28.L2 | 52.07,51.43 52.07,48.26 D28.J2 | 52.07,51.43 52.07,53.34 D28.F2 | 52.07,38.1 60.96,29.21 64.77,29.21 D27.R2 | 52.07,31.75 64.14,19.69 67.94,19.69 D27.U2 | D26.R2 78.11,27.94 78.11,24.13 79.38,22.86 79.38,20.95 80.64,19.69 D26.U2 | D24.U2 106.05,19.69 104.78,20.95 104.78,26.67 103.5,27.94 D24.R2 | 77.47,44.45 77.47,46.99 D26.J2 77.47,48.26 73.66,48.26 72.39,49.53 64.77,49.53 | 77.47,44.45 77.47,41.91 D26.L2 | D27.N2 64.77,35.56 64.77,40.64 D27.L2
  Bottom 0.508: 64.77,49.53 64.77,48.26 D27.J2 | 64.77,49.53 64.77,51.43 | 64.77,51.43 64.77,53.34 D27.F2 | D24.L2 103.5,41.91 103.5,46.99 D24.J2 102.87,48.26 102.87,53.34 D24.F2 | 90.17,51.43 90.17,48.26 D25.J2 | 90.17,51.43 90.17,53.34 D25.F2 | 90.17,51.43 81.28,60.32 81.28,62.87 D26.C2 | 77.47,44.45 86.36,35.56 90.17,35.56 D25.N2 | 64.77,51.43 55.88,60.32 55.88,62.87 D28.C2 | 52.07,51.43 43.18,60.32 43.18,62.87 D29.C2 | D04.C2 360.68,62.87 360.68,60.32 365.76,55.24 368.94,55.24 369.57,54.61 D03.F2 369.57,53.34 369.57,48.26 D03.J2 369.57,46.99 369.57,41.91 D03.L2 370.2,40.64 374.01,40.64 382.27,32.38 | 382.27,32.38 382.27,34.29 D02.N2 382.27,35.56 382.27,40.64 D02.L2 | 382.27,32.38 382.27,29.21 D02.R2 382.9,27.94 384.18,26.67 384.18,24.77 385.44,23.5 385.44,19.69 D02.U2 | 394.33,55.24 391.16,55.24 386.08,60.32 386.08,62.87 D02.C2 | 394.33,55.24 394.97,54.61 D01.F2 394.97,53.34 394.97,48.26 D01.J2 | 394.33,55.24 v394.33,56.52 | 394.97,38.73 394.97,35.56 D01.N2 | 394.97,38.73 394.97,40.64 D01.L2 | D01.U2 398.14,19.69 398.14,23.5 396.88,24.77 396.88,26.67 395.61,27.94 D01.R2 | 394.97,38.73 386.71,46.99 382.9,46.99 D02.J2 | D05.L2 344.81,40.64 346.71,40.64 347.35,40.01 349.25,40.01 353.06,36.2 356.24,36.2 356.87,35.56 D04.N2 | D04.R2 356.87,29.21 356.87,34.29 D04.N2 | 372.75,22.86 372.75,23.5 371.48,24.77 371.48,26.67 370.2,27.94 D03.R2 | 372.75,22.86 372.75,19.69 D03.U2 | 361.31,34.29 357.5,34.29 D04.N2 | 361.31,34.29 372.75,22.86 | 331.47,51.43 331.47,53.34 D06.F2 | 331.47,51.43 331.47,48.26 D06.J2 | 331.47,51.43 322.58,60.32 322.58,62.87 D07.C2 | 356.87,43.81 356.87,46.99 D04.J2 356.87,48.26 356.87,53.34 D04.F2 356.87,54.61 356.24,55.24 353.06,55.24 347.98,60.32 347.98,62.87 D05.C2
  Bottom 0.508: 356.87,43.81 356.87,41.91 D04.L2 | 344.17,51.43 344.17,53.34 D05.F2 | 344.17,51.43 344.17,48.26 D05.J2 | 344.17,51.43 335.28,60.32 335.28,62.87 D06.C2 | 361.31,34.29 361.31,36.83 362.58,38.1 356.87,43.81 | D17.R2 191.77,29.21 191.77,34.29 D17.N2 191.77,35.56 187.96,35.56 184.15,39.37 | D19.L2 167,40.64 170.81,40.64 172.09,39.37 174.62,39.37 177.8,42.55 179.07,41.27 D18.L2 179.71,40.64 180.97,39.37 | 180.97,39.37 184.15,39.37 | 184.15,39.37 175.9,47.62 173.99,45.72 172.09,45.72 167,50.8 167,53.34 D19.F2 | 206.38,24.13 v209.55,20.95 | 206.38,24.13 206.38,26.67 205.1,27.94 D16.R2 | 206.38,24.13 212.09,24.13 216.53,19.69 220.34,19.69 D15.U2 | v215.9,33.02 217.17,31.75 217.17,29.21 D15.R2 | D15.N2 217.17,35.56 217.17,40.64 D15.L2 217.17,41.91 213.36,41.91 210.82,44.45 210.19,44.45 | 210.19,44.45 207.65,41.91 205.1,41.91 D16.L2 | 210.19,44.45 208.28,46.35 205.74,46.35 205.1,46.99 D16.J2 204.47,48.26 204.47,53.34 D16.F2 | D15.J2 217.17,48.26 217.17,50.8 v215.9,52.07 208.91,59.05 208.91,62.23 208.28,62.87 D16.C2 | v204.47,37.47 204.47,35.56 D16.N2 | D19.U2 169.54,19.69 169.54,23.5 168.28,24.77 168.28,26.67 167,27.94 D19.R2 | v156.84,22.86 154.31,25.4 154.31,27.94 D20.R2 | 175.9,29.84 178.44,29.84 179.07,29.21 | 175.9,29.84 175.26,29.84 170.81,34.29 167,34.29 D19.N2 | 179.07,29.21 D18.R2 179.07,29.21 | 179.07,29.21 179.07,34.29 D18.N2 179.71,35.56 178.44,36.83 180.97,39.37 | 175.9,29.84 182.25,23.5 182.25,19.69 D18.U2 | D14.L2 230.5,41.91 233.04,41.91 235.59,44.45 234.31,45.72 231.78,45.72 230.5,46.99 D14.J2 229.87,48.26 229.87,50.8 227.33,53.34 | 227.33,53.34 221.62,59.05 221.62,62.23 220.98,62.87 D15.C2
  Bottom 0.508: 227.33,53.34 v227.33,52.7 | D14.U2 233.04,19.69 231.78,20.95 231.78,22.86 230.5,24.13 230.5,27.94 D14.R2 230.5,29.21 233.04,29.21 236.22,32.38 | 236.22,32.38 238.76,29.84 239.4,29.84 | 236.22,32.38 234.31,34.29 230.5,34.29 D14.N2 | 239.4,29.84 241.94,29.84 242.57,29.21 D13.R2 | 239.4,29.84 245.75,23.5 245.75,19.69 D13.U2 | 243.21,37.47 243.21,40.64 D13.L2 | 243.21,37.47 243.21,35.56 D13.N2 | 252.73,29.21 251.46,29.21 243.21,37.47 | 252.73,29.21 255.27,29.21 D12.R2 | 252.73,29.21 257.81,24.13 257.81,20.32 258.44,19.69 D12.U2 | D06.L2 331.47,40.64 331.47,35.56 D06.N2 332.11,34.29 335.92,34.29 347.35,22.86 | 347.35,22.86 347.35,23.5 346.07,24.77 346.07,26.67 344.81,27.94 D05.R2 | 347.35,22.86 347.35,19.69 D05.U2 | D08.R2 306.07,29.21 306.07,34.29 D08.N2 306.07,35.56 306.07,36.2 | 306.07,36.2 306.07,40.64 D08.L2 | D07.U2 321.94,19.69 321.94,23.5 320.68,24.77 320.68,26.67 319.4,27.94 D07.R2 | D12.N2 255.27,35.56 255.27,40.64 D12.L2 | D13.C2 246.38,62.87 246.38,60.32 251.46,55.24 254.63,55.24 255.27,54.61 D12.F2 255.27,53.34 255.27,48.26 D12.J2 | D12.C2 259.08,62.87 259.71,62.23 259.71,59.69 264.8,54.61 267.97,54.61 D11.F2 267.97,53.34 267.97,48.26 D11.J2 268.61,46.99 272.42,46.99 276.86,42.55 280.04,42.55 280.67,41.91 D10.L2 280.67,40.64 280.67,35.56 D10.N2 280.67,34.29 280.67,32.38 | 282.57,20.95 279.4,20.95 274.95,25.4 273.69,25.4 271.14,27.94 268.61,27.94 D11.R2 | 282.57,20.95 283.85,19.69 D10.U2 | D11.N2 267.97,35.56 267.97,40.64 D11.L2 268.61,40.64 272.42,40.64 280.67,32.38 | 280.67,32.38 280.67,29.21 D10.R2 281.31,27.94 282.57,26.67 | 282.57,26.67 282.57,20.95
  Bottom 0.508: D09.C2 297.18,62.87 297.18,60.32 302.26,55.24 305.44,55.24 306.07,54.61 D08.F2 306.07,53.34 306.07,48.26 D08.J2 | D11.C2 271.78,62.87 271.78,60.32 276.86,55.24 280.04,55.24 280.67,54.61 D10.F2 | D10.J2 280.67,48.26 280.67,53.34 D10.F2 | 284.48,60.32 284.48,62.87 D10.C2 | 284.48,60.32 289.56,55.24 292.74,55.24 293.37,54.61 D09.F2 293.37,53.34 293.37,48.26 D09.J2 293.37,46.99 293.37,44.45 | 293.37,44.45 293.37,41.91 D09.L2 | D09.U2 296.55,19.69 296.55,23.5 295.27,24.77 295.27,26.67 294,27.94 D09.R2 293.37,29.21 293.37,34.29 D09.N2 293.37,34.92 292.1,36.2 282.57,26.67 | 284.48,60.32 282.57,58.42 282.57,55.88 281.31,54.61 D10.F2 | 306.07,36.2 301.62,36.2 293.37,44.45 | D07.F2 318.77,54.61 315.6,54.61 310.51,59.69 310.51,62.23 309.88,62.87 D08.C2 | A01.L2 394.97,247.02 394.97,241.94 A01.N2 394.97,240.66 394.97,235.59 A01.R2 395.61,234.31 396.88,233.05 396.88,231.14 399.42,228.6 399.42,227.97 400.05,227.33 398.78,226.06 A01.U2 | 394.97,257.81 394.97,254.64 A01.J2 | 394.97,257.81 394.97,259.71 A01.F2 394.97,260.99 394.33,261.62 398.14,265.43 398.14,269.24 A01.C2 | 394.97,257.81 386.08,266.7 386.08,269.24 A02.C2 | A03.U2 372.75,226.06 369.57,226.06 361.31,234.31 361.31,236.86 362.58,238.12 361.31,239.4 358.77,239.4 357.5,240.66 A04.N2 | A04.U2 360.05,226.06 360.05,228.6 358.14,230.5 358.14,231.78 357.5,232.41 357.5,234.31 A04.R2 | v393.06,201.93 394.33,200.66 398.14,200.66 B01.C2 | A02.J2 382.27,254.64 382.27,259.71 A02.F2 | A03.R2 369.57,235.59 369.57,240.66 A03.N2 | v295.27,231.78 295.27,231.14 297.18,229.24 297.18,226.06 A09.U2 | A10.N2 281.31,240.66 285.12,240.66 289.56,236.22 292.74,236.22 293.37,235.59 A09.R2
